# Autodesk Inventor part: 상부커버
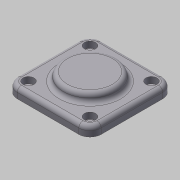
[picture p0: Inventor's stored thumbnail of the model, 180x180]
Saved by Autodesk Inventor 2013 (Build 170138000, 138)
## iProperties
Created: 2018-09
Part Number: 상부커버
Document SubType Name: Modeling
Density: 2.71 g/cm^3
Material: 알루미늄 6061
Mass: 115.577 g
Surface Area: 104.357 cm^2
Volume: 42.6483 cm^3
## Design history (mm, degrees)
sketch "스케치1"
  geometry: L1 (30, 22)-(30, -22); L2 (-22, 30)-(22, 30); L3 (-30, -22)-(-30, 22); L4 (22, -30)-(-22, -30); L5 (-30, 0)-(30, 0); L6 (0, 30)-(0, -30); C1 r 20 at (0, 0); A1 r 8 centre (22, 22) between (30, 22) and (22, 30); A2 r 8 centre (-22, 22) between (-22, 30) and (-30, 22); A3 r 8 centre (-22, -22) between (-30, -22) and (-22, -30); A4 r 8 centre (22, -22) between (22, -30) and (30, -22); 2 further points
  constraints: 12 end point, 8 point on circle, 7 midpoint, 7 tangent, 5 centre point, 3 equal radius, 2 horizontal, 1 coincident, 1 vertical
  dimensions: "d23" = 60 distance between parallel lines of L1 L3; "d25" = 60 distance between parallel lines of L4 L2; "d26" = 8 radius of A2; "d27" = 40 diameter of C1
extrude "돌출1" new body sketch "스케치1" distance "d0" = 7; taper "d1" = 0 deg
extrude "돌출2" join sketch "스케치1" distance "d2" = 10; taper "d3" = 0 deg
sketch "스케치2"
  geometry: C1 r 19 at (0, 0); 1 further point
  constraints: 1 centre point, 1 coincident
  dimensions: "d4" = 38 diameter of C1
extrude "돌출3" join sketch "스케치2" distance "d5" = 6; taper "d6" = 0 deg
fillet "모깎기1" dims "d7" = 3
fillet "모깎기2" dims "d8" = 3
sketch "스케치4"
  geometry: L1 (30, 22)-(30, -22) reference; L2 (-22, 30)-(22, 30) reference; L3 (-30, -22)-(-30, 22) reference; L4 (22, -30)-(-22, -30) reference; C1 r 22 at (0, 0) reference; A1 r 8 centre (-22, 22) between (-22, 30) and (-30, 22) reference; A2 r 8 centre (22, 22) between (30, 22) and (22, 30) reference; A3 r 8 centre (-22, 22) between (-22, 30) and (-30, 22) reference; A4 r 8 centre (-22, -22) between (-30, -22) and (-22, -30) reference; A5 r 8 centre (22, -22) between (22, -30) and (30, -22) reference; 5 further points
  constraints: 4 coincident
hole "구멍2" sketch "스케치4" at (-22, 22), (22, 22), (22, -22), (-22, -22) diameter "d28" = 4.5; stored, may be unused: countersink angle "d32" = 90 deg, drill point angle "d34" = 118 deg; dims "d29" = 6, "d30" = 8, "d31" = 4.5, "d33" = 8
fillet "모깎기3" dims "d19" = 3
chamfer "모따기1" distance "d20" = 1; stored, may be unused: second distance "d21" = 2, angle "d22" = 45 deg
node "솔리드1"
node "투영된 루프1"
